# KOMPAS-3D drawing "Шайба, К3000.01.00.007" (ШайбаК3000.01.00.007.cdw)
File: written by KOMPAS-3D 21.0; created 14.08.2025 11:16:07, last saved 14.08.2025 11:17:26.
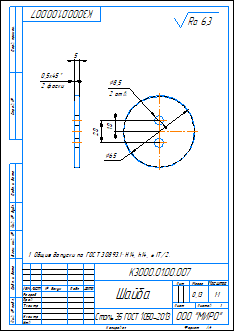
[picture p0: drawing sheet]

Sheet 1: A4, portrait

Document properties: Автор: admin; Полное имя файла: C:\Users\ShavarinML\Desktop\Стапель\2D\ШайбаК3000.01.00.007.cdw; Параметр неуказанной шероховатости: Ra 6,3; Масса: 0.125007

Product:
- Part/product: Шайба  | designation К3000.01.00.007
    Материал: Сталь 35 ГОСТ 1050-2013 (density 7826 kg/m3)
    Масса: 0.125007

Title block, sheet 1: Наименование: Шайба; designation: К3000.01.00.007; Материал: Сталь 35 ГОСТ 1050-2013; Масса: 0,13; Количество листов документа: 1; organisation: ООО "МИРО"; Форматы листов документа: A4

Views: Спереди 1, Спереди, Проекционный вид 2
Referenced files in C:\Users\ShavarinML\Desktop\Стапель\Из трубы\: Шайба.m3d
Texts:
  Ra 6,3
  К3000.01.00.007 Шайба
Dimensions and other numbers on the sheet: 5; 0,5; 2 фаски; 65; 20; 10; 8,5; 2 отв.; 1:1; 1; 0,13

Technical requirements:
  Общие допуски по ГОСТ 30893.1: H14, h14,   IT/2.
